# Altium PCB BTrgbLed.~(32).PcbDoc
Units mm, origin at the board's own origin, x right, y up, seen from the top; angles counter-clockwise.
Board outline 98.71 x 98.67 mm, 2 copper layers (Top Layer, Bottom Layer); 13 components, 12 nets, 62 pads, 7 vias.
Unrouted connection lines stored in the file: 1.
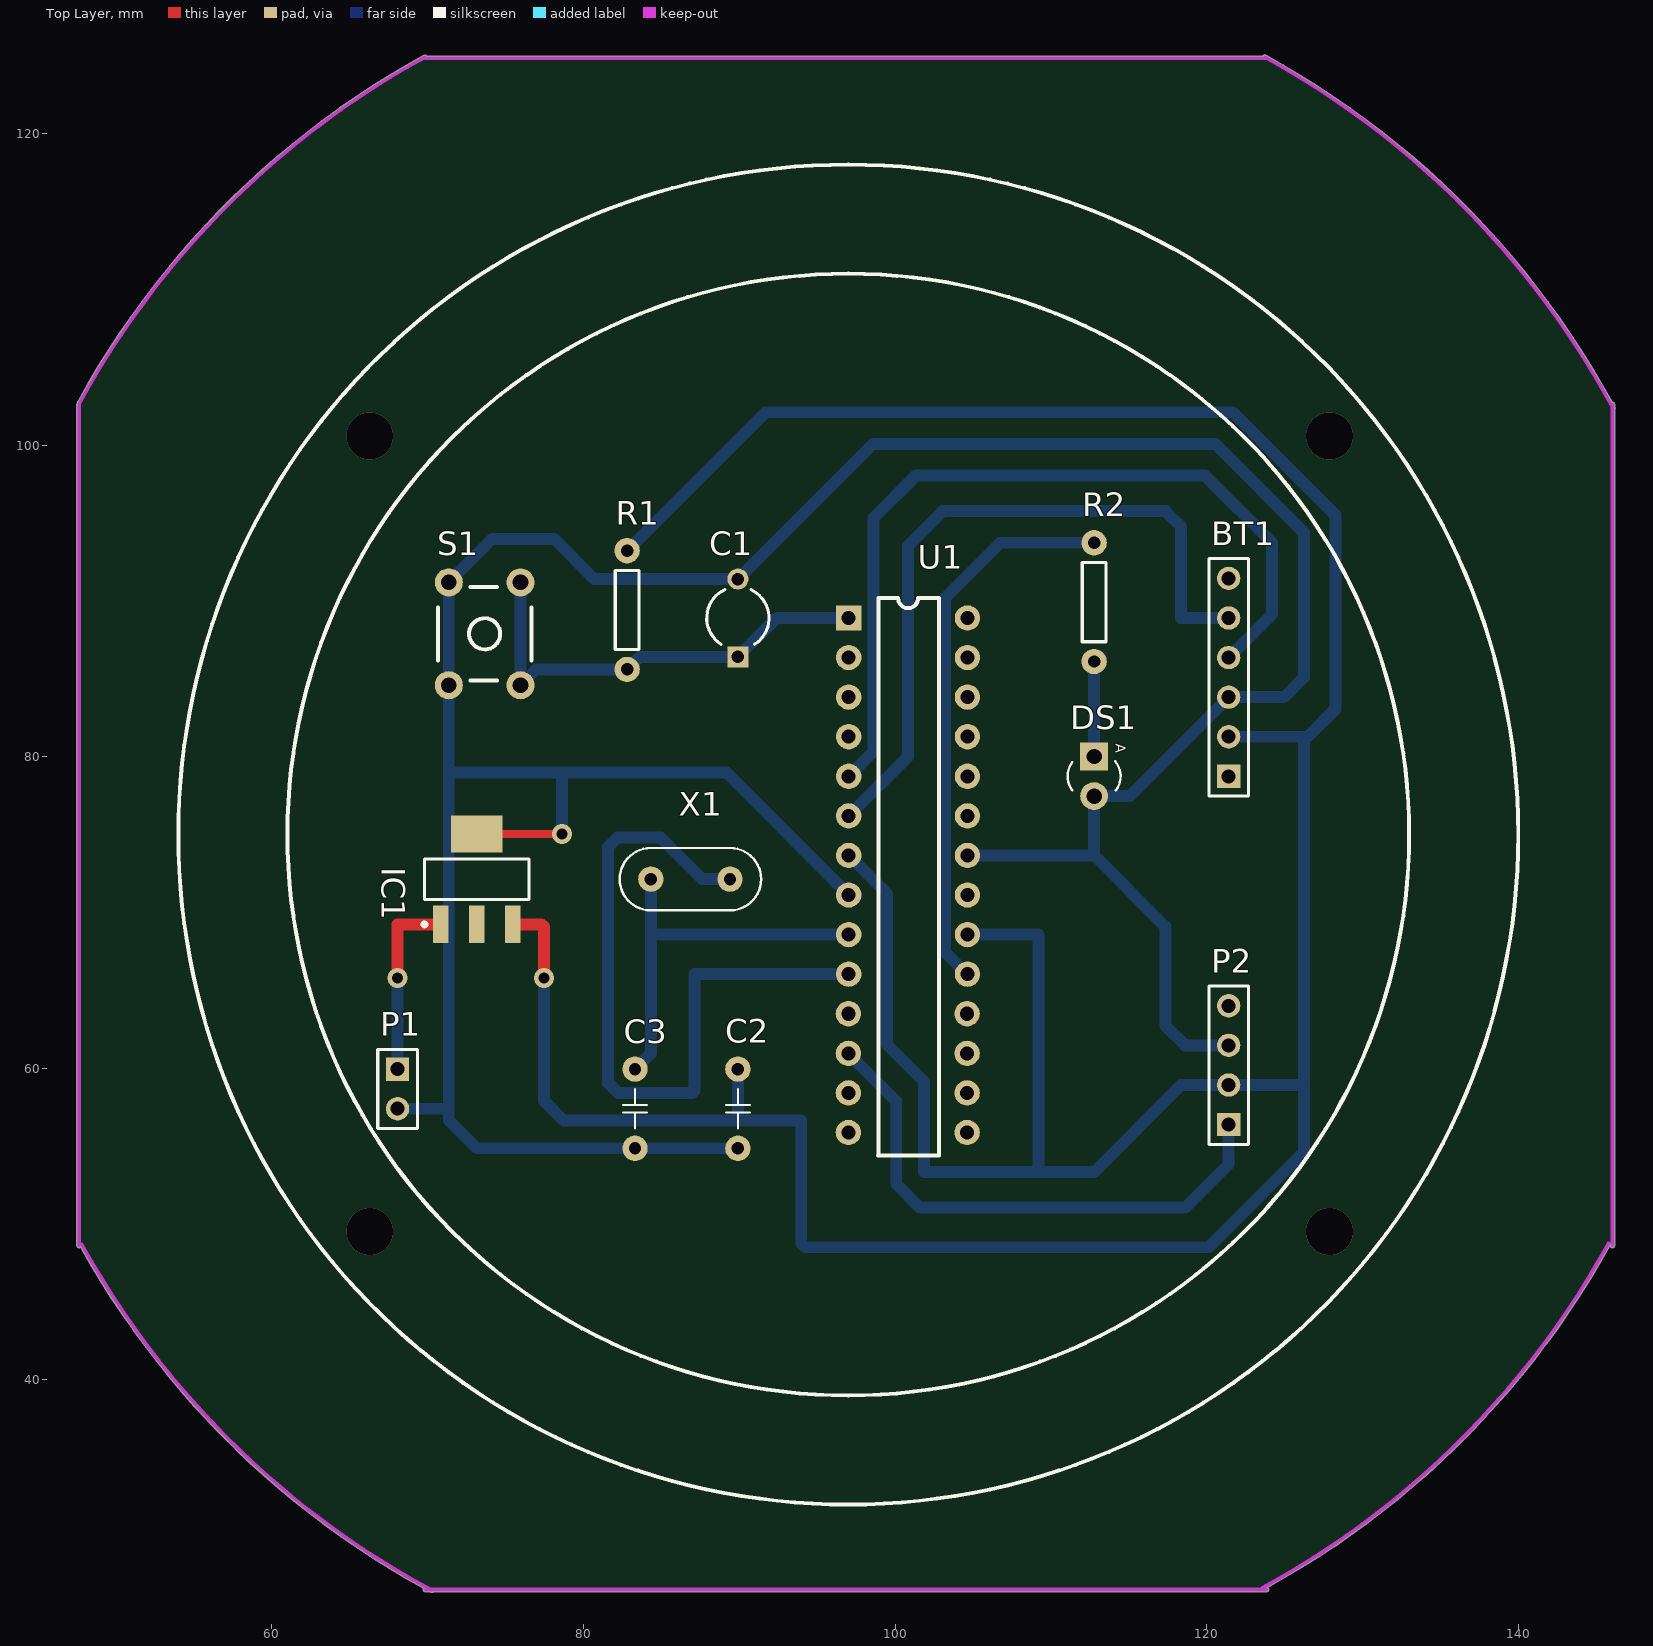
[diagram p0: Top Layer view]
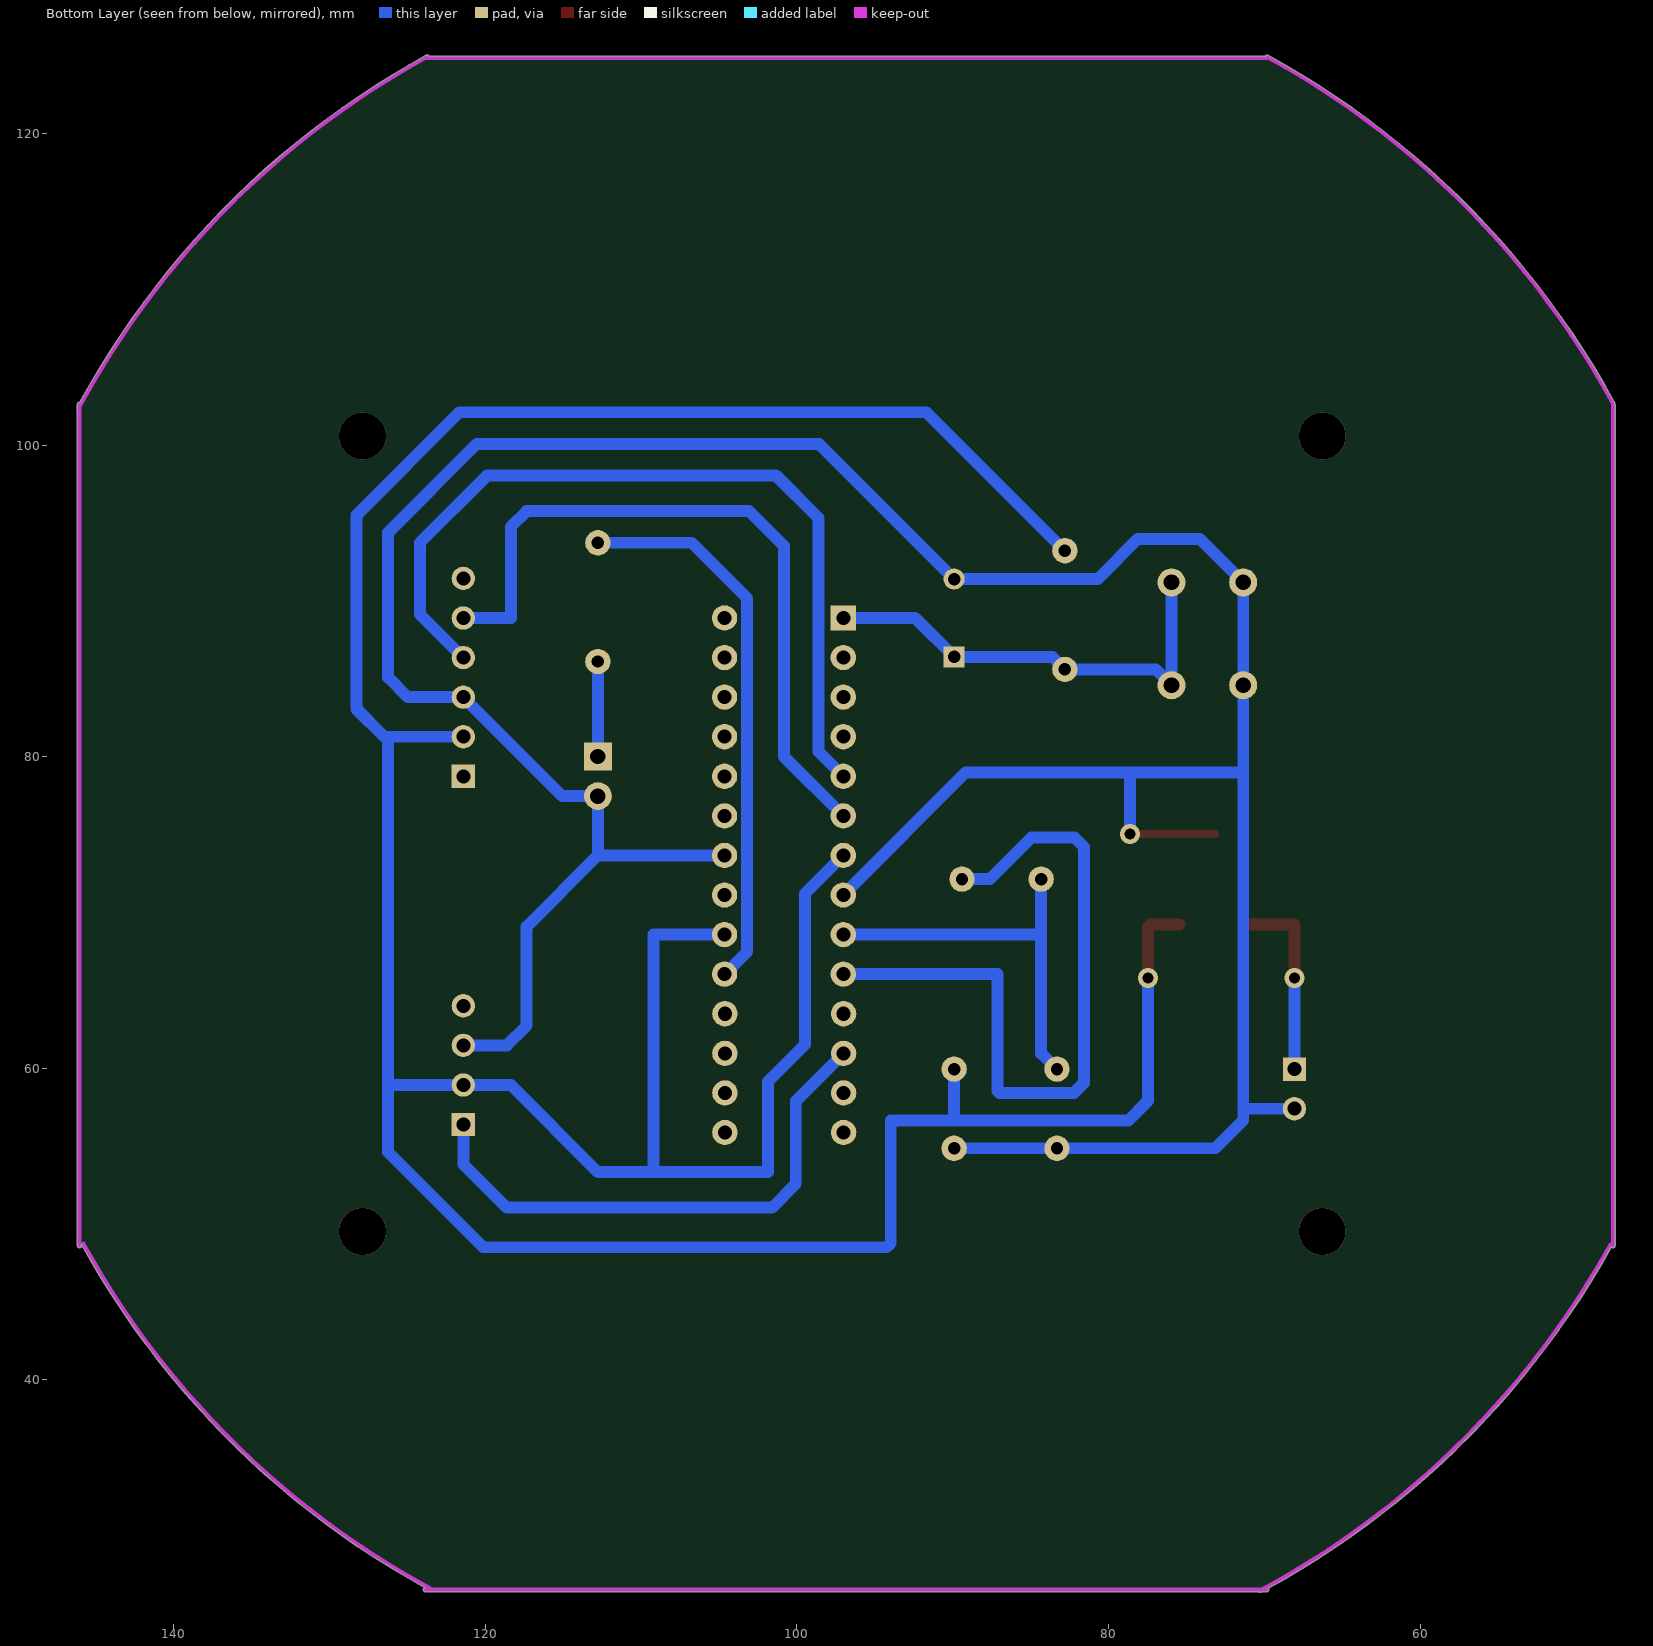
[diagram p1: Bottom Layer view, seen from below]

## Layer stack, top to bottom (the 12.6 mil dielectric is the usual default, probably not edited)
Top Layer: signal copper 0.0356
Dielectric: dielectric 0.32, FR-4, Dk 4.8
Bottom Layer: signal copper 0.0356

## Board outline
69.85,26.416 70.143,26.416 ccw(c96.781,75.819) 70.218,26.375 ccw(c70.279,26.487) 70.384,26.416 123.85,26.416 ccw(c123.85,26.543) 123.977,26.543 ccw(c123.85,26.543) 123.88,26.667 ccw(c96.781,75.819) 145.916,48.69 ccw(c145.805,48.751) 145.923,48.703 145.923,48.616 ccw(c146.05,48.616) 146.177,48.616 146.177,102.295 ccw(c146.082,102.379) 146.209,102.379 ccw(c146.082,102.379) 146.194,102.44 ccw(c96.781,75.819) 146.177,102.47 146.177,102.616 ccw(c146.05,102.616) 146.03,102.742 ccw(c96.781,75.819) 123.795,125.018 ccw(c123.734,124.906) 123.623,124.968 69.925,124.968 ccw(c69.817,124.9) 69.756,125.012 ccw(c96.781,75.819) 47.559,102.791 ccw(c47.671,102.73) 47.544,102.715 ccw(c47.625,102.616) 47.498,102.616 47.498,48.616 ccw(c47.625,48.616) 47.728,48.541 ccw(c96.781,75.819) 69.754,26.627 ccw(c69.85,26.543)

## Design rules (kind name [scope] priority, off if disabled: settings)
Clearance [All] p1: gap=0.254
PolygonConnect [All] p1: connectstyle=Relief reliefconductorwidth=0.254 reliefentries=4 polygonreliefangle="90 Angle"
RoutingLayers [All] p1: top layer_v5=FALSE bottom layer_v5=TRUE
RoutingVias [All] p1: holewidth=0.711 width=1.27 viastyle="Through Hole" minholewidth=0.711 minwidth=1.27 maxholewidth=0.711 maxwidth=1.27
SilkscreenOverComponentPads [All] p1: minsilkscreentomaskgap=0.254
SolderMaskExpansion [All] p1: expansion=0.102
Width [All] p1: maxlimit=1.016 minlimit=0.508 preferedwidth=0.762
26 further rules are at their usual default settings.

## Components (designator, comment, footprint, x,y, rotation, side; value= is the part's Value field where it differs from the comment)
BT1 "Bluetooth" Bluetooth 121.412,78.74 r90 top
C1 "47uF" CAPR5-4X5 89.916,88.9 r90 top
C2 "22pF" C200 89.916,57.404 r0 top
C3 "22pF" C200 83.312,57.404 r180 top
DS1 "TX-LED" LED-3mm_G 112.776,78.74 r270 top
IC1 "AM1117-5V" SOT-223 73.152,72.136 r90 top
P1 "12V" HDR1X2 68.072,59.944 r270 top
P2 "環形LED燈" HDR1X4 121.412,56.388 r90 top
R1 "10k" AXIAL-0.3 82.804,89.408 r270 top
R2 "220" AXIAL-0.3 112.776,89.916 r90 top
S1 "SW-PB" TACK6 73.66,87.884 r90 top
U1 "ATmega328" DIP-28 97.028,88.9 r270 top
X1 "16MHz" XTAL4-8 86.868,72.136 r0 top

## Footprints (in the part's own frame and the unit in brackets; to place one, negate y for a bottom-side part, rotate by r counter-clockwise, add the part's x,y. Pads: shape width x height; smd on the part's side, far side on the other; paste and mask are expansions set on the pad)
AXIAL-0.3 [mil] "0.3\" Resistor; 2 Leads"
  round 64 hole 31.5: 1(-150,0) 2(150,0)
  silkscreen extent -100,-30 100,30, body extent -161,-39 165,39, height 86
Bluetooth [mm]
  rect 1.5x1.5 hole 0.9: 1(0,0)
  round 1.5 hole 0.9: 2(2.54,0) 3(5.08,0) 4(7.62,0) 5(10.16,0) 6(12.7,0)
  silkscreen extent -1.27,-1.27 13.97,1.27, body extent -1.25,-1.3 13.97,1.28, height 11
C200 [mil] "塑膠電容器"
  round 64 hole 31.5: 1(0,100) 2(0,-100)
  silkscreen extent -30,-50 30,50, body extent -41,-136 39,135, height 354
CAPR5-4X5 [mm] "Capacitor; 2 Leads"
  rect 1.35x1.35 hole 0.8: 1(-2.5,0)
  round 1.35 hole 0.8: 2(2.5,0)
  silkscreen extent -1.69,-2 1.82,2
DIP-28 [mil]
  rect 64x64 hole 35.43: 1(0,0)
  round 64 hole 35.43: 2(100,0) 3(200,0) 4(300,0) 5(400,0) 6(500,0) 7(600,0) 8(700,0) 9(800,0) 10(900,0) 11(1000,-0.79) 12(1100,-0.79) 13(1200,-0.79) 14(1300,-0.79) 15(1300,299.21) 16(1200,299.21) 17(1100,299.21) 18(1000,299.21) 19(900,300) 20(800,300) 21(700,300) 22(600,300) 23(500,300) 24(400,300) 25(300,300) 26(200,300) 27(100,300) 28(0,300)
  silkscreen extent -50,74 1358,228, body extent -53,-5 1358,304, height 209
HDR1X2 [mm] "Connector; Header; 2 Position"
  rect 1.5x1.5 hole 0.9: 1(0,0)
  round 1.5 hole 0.9: 2(2.54,0)
  silkscreen extent -1.27,-1.27 3.81,1.27
HDR1X4 [mm] "Connector; Header; 4 Position"
  rect 1.5x1.5 hole 0.9: 1(0,0)
  round 1.5 hole 0.9: 2(2.54,0) 3(5.08,0) 4(7.62,0)
  silkscreen extent -1.27,-1.27 8.89,1.27
LED-3mm_G [mil] "3mm LED_Green"
  rect 70x70 hole 39: 1(-50,0)
  round 70 hole 39: 2(50,0)
  silkscreen extent -38,-67 35,67, body extent -66,-68 67,66, height 181
SOT-223 [mm] "SOT223, 4-Leads, Body 6.7x7.3mm (max), Pitch 2.30mm, IPC Medium Density"
  rect 2.4x1 smd: 1(-2.9,2.3) 2(-2.9,0) 3(-2.9,-2.3)
  rect 2.4x3.3 smd: 2(2.9,0)
  silkscreen extent -3.02,-3.35 1.3,3.47, body extent -1.86,-3.35 1.86,3.35, height 1.8
TACK6 [mm]
  round 1.8 hole 1: 1(-3.3,2.3) 1(3.3,2.3) 2(-3.3,-2.3) 2(3.3,-2.3)
  silkscreen extent -3,-3 3,3, body extent -3,-3.01 3.08,3.04, height 8
XTAL4-8 [mil]
  round 64 hole 31.5: 1(-100,0) 2(100,0)
  silkscreen extent -179,-79 179,79, body extent -178,-80 192,79, height 157

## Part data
C1: library part "Cap Pol1", "Polarized Capacitor (Radial)"
C2 C3: library part Cap, "Capacitor"
DS1: library part LED, "Typical INFRARED GaAs LED"
IC1: library part AM1117
P1: library part "Header 2", "Header, 2-Pin"
P2: library part "Header 4", "Header, 4-Pin"
R1 R2: library part Res, "Resistor"
S1: "Switch"
U1: "Arduino"
X1: library part XTAL, "Crystal Oscillator"

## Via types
v1: diameter 3, hole 3, Top Layer to Bottom Layer, 4 vias
v2: diameter 1.27, hole 0.711, Top Layer to Bottom Layer, 3 vias

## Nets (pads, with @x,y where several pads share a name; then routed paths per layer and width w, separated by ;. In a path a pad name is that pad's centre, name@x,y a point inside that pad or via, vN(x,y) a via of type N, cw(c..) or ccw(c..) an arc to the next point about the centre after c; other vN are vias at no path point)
DI: P2.1 U1.12 | length 35.3
  Bottom Layer w0.762: U1.12 100.076,57.892 100.076,52.578 101.6,51.054 118.618,51.054 121.412,53.848 P2.1
DO: P2.4
GND: BT1.3 C1.2 C2.2 C3.1 DS1.2 IC1.2 P1.2 P2.3 S1.1 U1.8 U1.22 | length 213.4
  Top Layer w0.508: IC1.2@73.152,75.036 v2(78.634,75.036)
  Bottom Layer w0.762: P1.2 71.233,57.404 ; 71.614,78.994 78.634,78.994 ; v2(78.634,75.036) 78.634,78.994 ; C2.2 C3.1 73.152,54.864 71.36,56.656 71.36,84.584 71.36,91.184 74.156,93.98 78.114,93.98 80.694,91.4 C1.2 98.592,100.076 120.548,100.076 126.238,94.386 126.238,85.09 124.968,83.82 BT1.3 115.062,77.47 DS1.2 112.776,73.66 ; U1.8 89.154,78.994 78.634,78.994 ; U1.22 112.776,73.66 ; P2.3 118.618,61.468 117.348,62.738 117.348,69.088 112.776,73.66
NetC1_1: C1.1 R1.2 S1.2 U1.1 | length 29.5
  Bottom Layer w0.762: S1.2@75.96,91.184 75.96,84.584 76.974,85.598 R1.2 83.606,86.4 C1.1 92.416,88.9 U1.1
NetC2_2: U1.10 X1.2 | length 48.5
  Bottom Layer w0.762: 85.344,58.42 84.455,58.42 ; X1.2 87.63,72.136 84.963,74.803 82.169,74.803 81.585,74.219 81.585,59.055 82.22,58.42 84.455,58.42 ; U1.10 87.122,66.04 87.122,58.547 86.995,58.42 84.455,58.42
NetC3_2: C3.2 U1.9 X1.1 | length 25.2
  Bottom Layer w0.762: C3.2 84.328,60.96 X1.1 ; 84.455,68.58 U1.9
NetDS1_1: DS1.1 R2.1 | length 6.1
  Bottom Layer w0.762: DS1.1 R2.1
NetIC1_1: IC1.1 P1.1 | length 11.9
  Top Layer w0.762: v2(68.072,65.786) 68.072,69.088 ; 68.072,69.236 IC1.1
  Bottom Layer w0.762: P1.1 v2(68.072,65.786)
NetR2_2: R2.2 U1.19 | length 35.8
  Bottom Layer w0.762: U1.19 103.2,67.488 103.2,90.17 106.756,93.726 R2.2
RX: BT1.5 U1.6 | length 46.4
  Bottom Layer w0.762: U1.6 100.838,80.01 100.838,93.523 103.073,95.758 117.348,95.758 118.364,94.742 ; 118.364,94.488 118.364,88.9 BT1.5
TX: BT1.4 U1.5 | length 54.3
  Bottom Layer w0.762: U1.5 98.628,80.34 98.628,95.326 101.346,98.044 119.888,98.044 124.206,93.726 124.206,89.154 BT1.4
VCC: BT1.2 C2.1 IC1.3 P2.2 R1.1 U1.7 U1.20 | length 243.1
  Top Layer w0.762: IC1.3 77.322,69.236 ; v2(77.47,65.786) 77.47,69.088
  Bottom Layer w0.762: v2(77.47,65.786) 77.47,57.912 78.74,56.642 89.916,56.642 ; R1.1 91.694,102.108 121.666,102.108 128.27,95.504 128.27,83.058 126.492,81.28 BT1.2 ; C2.1 89.916,56.642 ; U1.7 99.492,71.196 99.492,61.519 101.854,59.157 101.854,53.34 109.22,53.34 ; U1.20 109.22,68.58 109.22,53.34 ; 126.238,58.674 126.238,54.61 120.142,48.514 94.234,48.514 93.98,48.768 93.98,56.642 89.916,56.642 ; 126.238,81.026 126.238,58.928 P2.2 118.364,58.928 112.776,53.34 109.22,53.34
pads on no net: BT1.1 BT1.6 U1.2 U1.3 U1.4 U1.11 U1.13 U1.14 U1.15 U1.16 U1.17 U1.18 U1.21 U1.23 U1.24 U1.25 U1.26 U1.27 U1.28
copper on no net:
  other v1: 66.294,49.53 127.889,49.53 66.294,100.584 127.889,100.584

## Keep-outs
Keep-Out Layer:
  lines w0.254: 47.625,48.616 47.625,102.616 ; 47.671,102.73 cw(c96.781,75.819) 69.817,124.9 ; 47.783,48.704 ccw(c96.781,75.819) 70.279,26.487 ; 69.85,26.543 123.85,26.543 ; 69.85,124.841 123.85,124.841 ; 123.584,26.65 ccw(c96.781,75.819) 145.805,48.751 ; 123.734,124.906 cw(c96.781,75.819) 146.082,102.379 ; 146.05,48.616 146.05,102.616

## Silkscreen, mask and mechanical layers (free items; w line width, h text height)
Top Overlay:
  circle w0.254: c97,75 r36
  circle w0.254: c97,75 r43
